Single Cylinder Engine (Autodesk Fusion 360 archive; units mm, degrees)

design "Single Cylinder Engine" references "Piston", "Piston Pin", "Connecting Rod", "Crank Case", "Crank Shaft"
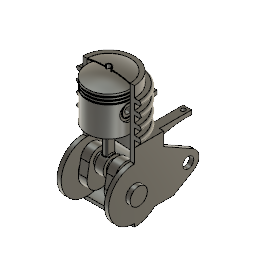
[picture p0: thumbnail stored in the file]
component_insert "Component Insert1"
ground "Ground1"
component_insert "Component Insert3"
joint "Assemble2" OffsetX 0 OffsetY 0 OffsetZ 0 AngleZ 0 OffsetX 0 OffsetY 0 OffsetZ 0 AngleZ 0 alignAngle 0 alignOffsetX 0 alignOffsetY 0 alignOffsetZ -10
component_insert "Component Insert4"
position "Position1"
joint "Assemble3" OffsetX 0 OffsetY 0 OffsetZ 0 AngleZ 0 OffsetX 0 OffsetY 0 OffsetZ 0 AngleZ 0 alignAngle 90 alignOffsetX 0 alignOffsetY 0 alignOffsetZ 0
component_insert "Component Insert6"
joint "Assemble4" OffsetX 0 OffsetY 0 OffsetZ 0 AngleZ 0 OffsetX 0 OffsetY 0 OffsetZ 0 AngleZ 0 alignAngle -90 alignOffsetX 0 alignOffsetY 0 alignOffsetZ 0
component_insert "Component Insert8"
position "Position2"
joint "Assemble5" OffsetX 0 OffsetY 0 OffsetZ 0 AngleZ 0 OffsetX 0 OffsetY 0 OffsetZ 0 AngleZ 0 alignAngle 90 alignOffsetX 0 alignOffsetY 0 alignOffsetZ 0
joint "Assemble7" OffsetX 0 OffsetY 0 OffsetZ 0 AngleZ 0 OffsetX 0 OffsetY 0 OffsetZ 0 AngleZ 0 alignAngle 90 alignOffsetX 0 alignOffsetY 0 alignOffsetZ 0

design "Piston"
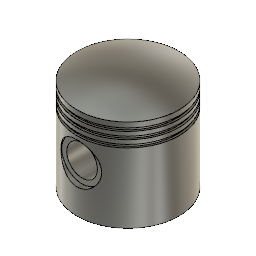
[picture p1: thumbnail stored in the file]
sketch "Sketch1" plane through (0, 0, 0) normal (0, 1, 0) x axis (1, 0, 0)
  line L1 (0, -80) -> (0, 0)
  line L2 (72.9805, 0) -> (0, 0)
  line L3 (50, -68.3994) -> (50, 0)
  line L4 (43, 0) -> (50, 0)
  line L5 (43, 0) -> (43, -20)
  line L6 (48, -68.3994) -> (50, -68.3994)
  line L7 (48, -71.3994) -> (48, -68.3994)
  line L8 (50, -71.3994) -> (48, -71.3994)
  line L9 (50, -75.3994) -> (50, -71.3994)
  line L10 (48, -75.3994) -> (50, -75.3994)
  line L11 (48, -78.3994) -> (48, -75.3994)
  line L12 (50, -78.3994) -> (48, -78.3994)
  line L13 (50, -82.3994) -> (50, -78.3994)
  line L14 (48, -82.3994) -> (50, -82.3994)
  line L15 (48, -85.3994) -> (48, -82.3994)
  line L16 (50, -85.3994) -> (48, -85.3994)
  line L17 (50, -90.3994) -> (50, -85.3994)
  line L18 (37.5, -20) -> (37.5, -84)
  line L19 (37.5, -20) -> (43, -20)
  line L20 (0, -84) -> (0, -100)
  line L21 (37.5, -84) -> (0, -84)
  arc A1 centre (0, 35) radius 135 clockwise from (50, -90.3994) to (0, -100)
  point P1 (0, 0)
  point P2 (0, 0)
  point P4 (0, 0)
  point P6 (50, 0)
  point P8 (43, 0)
  point P22 (0, -100)
  point P23 (0, 35)
  point P9 (43, -20)
  point P10 (48, -68.3994)
  point P11 (48, -71.3994)
  point P7 (50, -68.3994)
  point P12 (50, -71.3994)
  point P13 (50, -75.3994)
  point P20 (50, -85.3994)
  point P21 (50, -90.3994)
  point P26 (0, -84)
  coincident P1 P2
  vertical L1
  coincident P1 P4
  perpendicular L1 L2
  coincident L2 P6
  perpendicular L2 L3
  coincident L2 P8
  perpendicular L2 L5
  perpendicular L3 L6
  perpendicular L6 L7
  perpendicular L7 L8
  perpendicular L6 L9
  perpendicular L9 L10
  perpendicular L10 L11
  perpendicular L11 L12
  perpendicular L12 L13
  perpendicular L11 L14
  perpendicular L14 L15
  perpendicular L11 L16
  perpendicular L16 L17
  equal L7 L11
  equal L11 L15
  collinear L7 L11
  collinear L11 L15
  equal L9 L13
  collinear L13 L17
  collinear L9 L13
  collinear L3 L9
  coincident L1 P22
  horizontal L19
  parallel L1 L20
  horizontal L21
  vertical P1 P23
  dimension "d1" = 100
  dimension "d2" = 86
  dimension "d3" distance P8 P9 = 20
  dimension "d4" distance P10 P11 = 3
  dimension "d5" distance P7 P10 = 2
  dimension "d6" distance P12 P13 = 4
  dimension "d7" distance P20 P21 = 5
  dimension "d8" radius A1 = 135
  dimension "d9" = 75
  dimension "d10" distance L2 P22 = 100
  dimension "d11" distance P22 P26 = 16
revolve "Revolve1" sketch "Sketch1" AlongAngle 360
sketch "Sketch2" plane through (0, 0, 0) normal (0, 1, 0) x axis (1, 0, 0)
  circle C1 centre (0, -45) radius 15
  point P1 (0, 0)
  point P2 (0, -45)
  vertical P1 P2
  dimension "d14" diameter C1 = 30
  dimension "d15" distance P1 P2 = 45
extrude "Extrude1" cut sketch "Sketch2" no distance stored
work_plane "WorkPlane1" AlongDistance -20
sketch "Sketch4" plane through (0, -20, 0) normal (0, 1, 0) x axis (1, 0, 0)
  circle C1 centre (0, -45) radius 15
  circle C2 centre (0, -45) radius 20
  point P1 (0, 0)
  point P2 (0, -45)
  vertical P1 P2
  concentric C1 C2
  dimension "d25" diameter C1 = 30
  dimension "d26" distance P1 P2 = 45
  dimension "d27" diameter C2 = 40
extrude "Extrude3" add sketch "Sketch4" to an object
mirror "Mirror2"
work_plane "WorkPlane2" AlongDistance -50
sketch "Sketch5" plane through (0, -50, 0) normal (0, 1, 0) x axis (1, 0, 0)
  circle C1 centre (0, -45) radius 20
  circle C2 centre (0, -45) radius 20
  concentric C1 C2
  dimension "d32" diameter C1 = 40
extrude "Extrude4" cut sketch "Sketch5" along normal blind 5
mirror "Mirror3"

design "Crank Case"
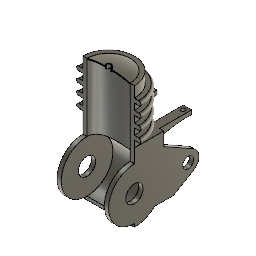
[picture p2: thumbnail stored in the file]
sketch "Sketch1" plane through (0, 0, 0) normal (1, 0, 0) x axis (0, 1, 0)
  line L1 (0, 160) -> (0, 0)
  line L2 (68, 160) -> (0, 160)
  line L3 (68, 68) -> (68, 160)
  arc A1 centre (0, 68) radius 68 clockwise from (68, 68) to (0, 0)
  point P1 (0, 0)
  point P2 (0, 0)
  point P6 (0, 0)
  point P3 (0, 160)
  point P4 (68, 160)
  coincident P1 P2
  vertical L1
  perpendicular L1 L2
  perpendicular L2 L3
  coincident P1 P6
  tangent L3 A1
  dimension "d1" distance P2 P3 = 160
  dimension "d2" distance P3 P4 = 68
  dimension "d3" radius A1 = 68
extrude "Extrude1" new body distance 120
sketch "Sketch2" plane through (0, 0, 0) normal (0, -1, 0) x axis (1, 0, 0)
  line L1 (60, 0) -> (-60, 0)
  line L2 (60, 160) -> (60, 0)
  line L3 (-60, 160) -> (60, 160)
  line L4 (-60, 0) -> (-60, 160)
  line L5 (60, 200) -> (60, 185)
  line L6 (70, 175) -> (60, 175)
  line L7 (70, 225) -> (60, 225)
  line L8 (60, 185) -> (70, 185)
  line L9 (60, 235) -> (70, 235)
  line L10 (60, 285) -> (60, 260)
  line L11 (5, 286) -> (5, 295)
  line L12 (7, 295) -> (7, 291)
  line L13 (7, 286) -> (5, 286)
  line L14 (5, 295) -> (7, 295)
  line L15 (60, 260) -> (70, 260)
  line L16 (7, 289) -> (7, 286)
  line L17 (50, 285) -> (60, 285)
  line L18 (70, 250) -> (60, 250)
  line L19 (60, 250) -> (60, 235)
  line L20 (50, 282.9194) -> (50, 160)
  line L21 (60, 225) -> (60, 210)
  line L22 (60, 210) -> (70, 210)
  line L23 (0, 288.3131) -> (0, 0)
  line L24 (70, 200) -> (60, 200)
  line L25 (60, 175) -> (60, 160)
  line L26 (60, 160) -> (50, 160)
  arc A1 centre (70, 205) radius 5 clockwise from (70, 210) to (70, 200)
  arc A2 centre (70, 180) radius 5 clockwise from (70, 185) to (70, 175)
  arc A3 centre (70, 255) radius 5 clockwise from (70, 260) to (70, 250)
  arc A4 centre (70, 230) radius 5 clockwise from (70, 235) to (70, 225)
  arc A5 centre (7.0116, 134) radius 157 clockwise from (7, 291) to (50, 285)
  arc A6 centre (7.0116, 134) radius 155 clockwise from (7, 289) to (50, 282.9194)
  point P20 (0, 0)
  point P25 (0, 0)
  point P13 (60, 185)
  point P39 (7, 291)
  point P1 (0, 0)
  point P15 (60, 160)
  point P28 (50, 160)
  point P11 (70, 180)
  point P29 (60, 285)
  point P7 (5, 295)
  point P33 (5, 286)
  point P38 (7, 289)
  point P32 (50, 285)
  coincident P20 P25
  perpendicular L6 L25
  tangent L6 A2
  coincident P13 L25
  tangent L8 A2
  perpendicular L8 L25
  collinear L5 L25
  collinear L5 L21
  collinear L19 L21
  collinear L10 L19
  perpendicular L10 L17
  vertical L11
  perpendicular L11 L13
  perpendicular L13 L16
  horizontal L14
  coincident P39 L16
  collinear L12 L16
  coincident P1 P25
  coincident L3 P15
  coincident L2 P15
  coincident L3 P28
  concentric A5 A6
  dimension "d14" radius A2 = 5
  dimension "d15" distance P11 P15 = 20
  dimension "d16" distance P15 P29 = 125
  dimension "d17" distance P11 P15 = 10
  dimension "d19" = 100
  dimension "d20" = 10
  dimension "d21" = 14
  dimension "d22" distance P7 P33 = 9
  dimension "d23" distance P38 L13 = 3
  dimension "d29" distance L14 L26 = 135
  dimension "d30" distance P29 P32 = 10
  dimension "d31" radius A5 = 157
  dimension "d32" radius A6 = 155
  dimension "d12" R-Pattern1-uDistance = 25
  dimension "d13" R-Pattern1-vDistance = 0
revolve "Revolve1" sketch "Sketch2" AlongAngle -180
sketch "Sketch3" plane through (60, 0, 0) normal (1, 0, 0) x axis (0, 1, 0)
  line L1 (0, 0) -> (0, 160)
  line L2 (68, 160) -> (68, 68)
  line L3 (0, 160) -> (68, 160)
  arc A1 centre (0, 68) radius 68 clockwise from (68, 68) to (0, 0)
  circle C1 centre (0, 68) radius 60
  concentric A1 C1
  dimension "d34" diameter C1 = 120
extrude "Extrude2" cut sketch "Sketch3" profile of L1 C1 no distance stored
sketch "Sketch4" plane through (0, 0, 160) normal (0, 0, 1) x axis (-1, 0, 0)
  line L1 (-50, 0) -> (50, 0)
  arc A1 centre (0, 0) radius 50 clockwise from (50, 0) to (-50, 0)
  circle C1 centre (0, 0) radius 50
  concentric A1 C1
  equal A1 C1
extrude "Extrude3" cut sketch "Sketch4" to an object
sketch "Sketch6" plane through (60, 0, 0) normal (1, 0, 0) x axis (0, 1, 0)
  line L1 (0, 0) -> (0, 8)
  line L2 (68, 160) -> (68, 68)
  line L3 (0, 160) -> (68, 160)
  line L4 (0, 128) -> (0, 160)
  arc A1 centre (0, 68) radius 60 clockwise from (0, 128) to (0, 8)
  arc A2 centre (0, 68) radius 68 clockwise from (68, 68) to (0, 0)
  circle C1 centre (0, 68) radius 60
  circle C2 centre (0, 68) radius 20
  concentric A1 C1
  equal A1 C1
  concentric C1 C2
  dimension "d38" diameter C2 = 40
extrude "Extrude4" add sketch "Sketch6" profile of A1 C1 C2 against normal blind 10
mirror "Mirror1"
sketch "Sketch7" plane through (60, 0, 0) normal (1, 0, 0) x axis (0, 1, 0)
  line L1 (0, 0) -> (0, 8)
  line L2 (68, 160) -> (68, 68)
  line L3 (0, 160) -> (68, 160)
  line L4 (0, 128) -> (0, 160)
  line L5 (137.7314, 46.4846) -> (90.9301, 18.7906)
  line L6 (68, 128.7906) -> (137.2671, 89.7834)
  line L7 (90.9301, 18.7906) -> (46.9301, 18.7906)
  line L8 (188.2817, 68) -> (0, 68)
  circle C1 centre (0, 68) radius 20
  arc A1 centre (0, 68) radius 68 clockwise from (68, 68) to (0, 0)
  arc A2 centre (0, 68) radius 60 clockwise from (0, 8) to (0, 128)
  arc A3 centre (125, 68) radius 25 clockwise from (137.2671, 89.7834) to (137.7314, 46.4846)
  circle C2 centre (125, 68) radius 12.5
  point P13 (68, 128.7906)
  point P14 (46.9301, 18.7906)
  point P2 (0, 68)
  point P12 (125, 68)
  point P15 (0, 68)
  point P9 (90.9301, 18.7906)
  tangent L5 A3
  coincident L2 P13
  tangent A3 L6
  coincident A1 P14
  horizontal L7
  horizontal P2 P12
  coincident P2 P15
  horizontal L8
  concentric A3 C2
  dimension "d42" distance P9 P14 = 44
  dimension "d43" radius A3 = 25
  dimension "d45" angle L5 L6 = 60
  dimension "d46" distance P13 L7 = 110
  dimension "d47" distance P2 P12 = 125
  dimension "d51" diameter C2 = 25
extrude "Extrude5" add sketch "Sketch7" profile of A1 L2 L5 A3 L6 L7 C2 against normal blind 10
mirror "Mirror2"
work_plane "WorkPlane1" AlongDistance -10
sketch "Sketch8" plane through (50, 45.0767, 80) normal (1, 0, 0) x axis (0, 1, 0)
  line L1 (22.9233, 48.7906) -> (22.9233, 80)
  line L2 (97.9233, 80) -> (22.9233, 80)
  line L3 (97.9233, 70) -> (97.9233, 80)
  line L4 (22.9233, 60) -> (22.9233, 80)
  arc A1 centre (86.3789, -129.6665) radius 200 clockwise from (22.9233, 60) to (97.9233, 70)
  point P2 (22.9233, 80)
  point P5 (22.9233, 80)
  point P8 (22.9233, 60)
  point P3 (22.9233, 80)
  point P10 (22.9233, 80)
  point P6 (97.9233, 80)
  point P7 (97.9233, 70)
  coincident P2 P5
  perpendicular L1 L2
  perpendicular L2 L3
  coincident L1 P8
  coincident P3 P10
  dimension "d53" distance P5 P6 = 75
  dimension "d54" distance P6 P7 = 10
  dimension "d55" radius A1 = 200
  dimension "d56" distance P8 P10 = 20
extrude "Extrude6" add sketch "Sketch8" against normal blind 20
sketch "Sketch9" plane through (0, 0, 160) normal (0, 0, 1) x axis (-1, 0, 0)
  line L1 (-60, -68) -> (-60, 0)
  line L2 (-50, -68) -> (-60, -68)
  line L3 (-50, -143) -> (-50, -68)
  line L4 (-30, -143) -> (-50, -143)
  line L5 (-30, -68) -> (-30, -143)
  line L6 (60, -68) -> (-30, -68)
  line L7 (60, 0) -> (60, -68)
  arc A1 centre (0, 0) radius 60 clockwise from (60, 0) to (-60, 0)
  circle C1 centre (-40, -133) radius 5
  point P11 (-40, -133)
  dimension "d59" diameter C1 = 10
  dimension "d60" distance L4 P11 = 10
  dimension "d61" distance L5 P11 = 10
extrude "Extrude7" cut sketch "Sketch9" profile of C1 to an object
mirror "Mirror3"

design "Connecting Rod"
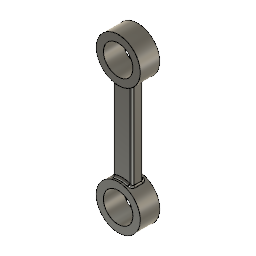
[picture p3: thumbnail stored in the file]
sketch "Sketch2" plane through (0, 0, 0) normal (0, 1, 0) x axis (1, 0, 0)
  circle C1 centre (0, 0) radius 15
  circle C2 centre (0, 0) radius 22.5
  point P1 (0, 0)
  point P2 (0, 0)
  point P3 (0, 0)
  coincident P1 P2
  coincident P1 P3
  dimension "d1" diameter C1 = 30
  dimension "d2" diameter C2 = 45
extrude "Extrude1" new body sketch "Sketch2" distance 20
sketch "Sketch3" plane through (0, 0, 0) normal (0, 1, 0) x axis (1, 0, 0)
  line L1 (10, -109.8444) -> (10, -20.1556)
  line L2 (-10, -20.1556) -> (-10, -109.8444)
  line L3 (0, -100.2996) -> (0, 0)
  circle C1 centre (0, 0) radius 22.5
  arc A1 centre (0, -130) radius 22.5 clockwise from (-10, -109.8444) to (10, -109.8444)
  point P1 (0, 0)
  point P2 (0, 0)
  point P3 (0, 0)
  point P5 (-10, -20.1556)
  point P6 (10, -20.1556)
  point P7 (0, -130)
  coincident P1 P2
  vertical L1
  vertical L2
  coincident P2 P3
  symmetric L1 L2 L3
  coincident C1 P5
  coincident C1 P6
  coincident L3 P7
  dimension "d5" distance L1 L2 = 20
  dimension "d8" distance P1 P7 = 130
  dimension "d9" radius A1 = 22.5
extrude "Extrude2" add sketch "Sketch3" profile of C1 L1 L2 A1 distance 12
sketch "Sketch4" plane through (0, 0, 0) normal (0, 1, 0) x axis (1, 0, 0)
  circle C1 centre (0, -130) radius 22.5
  arc A1 centre (0, -130) radius 22.5 clockwise from (-10, -109.8444) to (10, -109.8444)
  circle C2 centre (0, -130) radius 15
  concentric C1 A1
  concentric C1 C2
  equal C1 A1
  dimension "d12" diameter C2 = 30
extrude "Extrude3" add sketch "Sketch4" distance 20
fillet "Fillet1" radius 2
fillet "Fillet2" radius 2

design "Piston Pin"
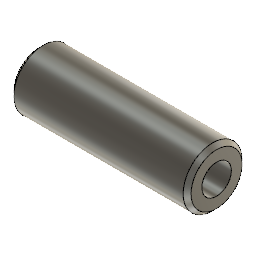
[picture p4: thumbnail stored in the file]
sketch "Sketch1" plane through (0, 0, 0) normal (1, 0, 0) x axis (0, 1, 0)
  circle C1 centre (0, 0) radius 15
  circle C2 centre (0, 0) radius 7.5
  point P1 (0, 0)
  point P2 (0, 0)
  coincident P1 P2
  concentric C1 C2
  dimension "d1" diameter C1 = 30
  dimension "d2" diameter C2 = 15
extrude "Extrude1" new body sketch "Sketch1" distance 90
chamfer "Chamfer1" distance 2

design "Crank Shaft"
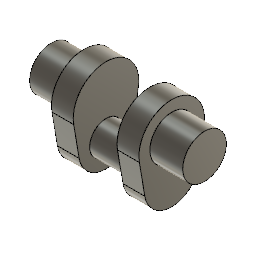
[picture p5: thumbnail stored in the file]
sketch "Sketch1" plane through (0, 0, 0) normal (1, 0, 0) x axis (0, 1, 0)
  circle C1 centre (0, 0) radius 15
  point P1 (0, 0)
  point P2 (0, 0)
  coincident P1 P2
  dimension "d1" diameter C1 = 30
extrude "Extrude1" new body sketch "Sketch1" distance 40
sketch "Sketch2" plane through (20, 0, 0) normal (1, 0, 0) x axis (0, 1, 0)
  line L1 (-29.5804, 25) -> (-24.6503, -4.1667)
  line L2 (29.5804, 25) -> (24.6503, -4.1667)
  circle C1 centre (0, 0) radius 15
  arc A1 centre (0, 0) radius 25 clockwise from (24.6503, -4.1667) to (-24.6503, -4.1667)
  arc A2 centre (0, 30) radius 30 clockwise from (-29.5804, 25) to (29.5804, 25)
  point P1 (0, 0)
  point P3 (0, 0)
  point P8 (0, 30)
  coincident P1 P3
  vertical P1 P8
  tangent A2 L1
  tangent A2 L2
  tangent A1 L2
  tangent A1 L1
  dimension "d4" radius A1 = 25
  dimension "d6" distance P3 P8 = 30
  dimension "d7" radius A2 = 30
extrude "Extrude2" add sketch "Sketch2" along normal blind 20
sketch "Sketch3" plane through (40, 0, 0) normal (1, 0, 0) x axis (0, 1, 0)
  line L1 (29.5804, 25) -> (24.6503, -4.1667)
  line L2 (-24.6503, -4.1667) -> (-29.5804, 25)
  arc A1 centre (0, 0) radius 25 clockwise from (24.6503, -4.1667) to (-24.6503, -4.1667)
  arc A2 centre (0, 30) radius 30 clockwise from (-29.5804, 25) to (29.5804, 25)
  circle C1 centre (0, 30) radius 20
  concentric A2 C1
  dimension "d10" diameter C1 = 40
extrude "Extrude3" add sketch "Sketch3" profile of C1 along normal blind 30
mirror "Mirror1"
